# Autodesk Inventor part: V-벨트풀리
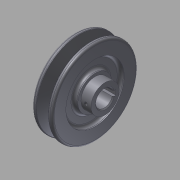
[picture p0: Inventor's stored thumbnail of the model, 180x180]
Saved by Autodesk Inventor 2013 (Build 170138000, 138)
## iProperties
Company: 한국ATC센터
Created: 2014-07
Part Number: V-벨트풀리
Document SubType Name: Modeling
Designer: KYOUNG IL JANG
Density: 7.87 g/cm^3
Material: 강철, 탄소
Mass: 593.766 g
Surface Area: 234.122 cm^2
Volume: 75.4468 cm^3
Author: KYOUNG IL JANG
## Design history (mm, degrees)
sketch "스케치1"
  geometry: L1 (-15, 0)-(15, 0); L2 (-15, 0)-(-15, 17); L3 (-15, 17)-(-11, 17); L4 (-11, 17)-(-11, 29); L5 (-11, 29)-(-15, 29); L6 (-15, 29)-(-15, 42.5); L7 (-15, 42.5)-(-10.976, 42.5); L8 (-10.976, 42.5)-(-7.154, 30); L9 (-7.154, 30)-(-2.846, 30); L10 (-2.846, 30)-(0.976, 42.5); L11 (0.976, 42.5)-(5, 42.5); L12 (5, 42.5)-(5, 29); L13 (5, 29)-(1, 29); L14 (1, 29)-(1, 17); L15 (1, 17)-(5, 17); L16 (5, 17)-(5, 14); L17 (5, 14)-(15, 14); L18 (15, 14)-(15, 0); L19 (-9.6, 38)-(-0.4, 38); 2 further points
  constraints: 38 end point, 11 parallel, 7 collinear, 3 equal length, 3 perpendicular, 2 point on line, 1 coincident, 1 horizontal, 1 midpoint
  dimensions: "d0" = 30 distance of L1.start L1.end; "d1" = 4.5 distance between parallel lines of L7 L19; "d2" = 8 distance between parallel lines of L9 L19; "d3" = 9.2 distance of L19.start L19.end; "d4" = 34 deg angle of L10 L8; "d5" = 20 distance between parallel lines of L12 L6; "d6" = 76 diameter of L19 L1; "d7" = 4 distance of L2.end L3.end; "d8" = 34 diameter of L3 L1; "d9" = 58 diameter of L5 L1; "d10" = 28 diameter of L17 L1
revolve "회전1" sketch "스케치1" stored, may be unused: angle "d11" = 90 deg
sketch "스케치2"
  geometry: L1 (-2.5, 8.124)-(-2.5, 10.8); L2 (-2.5, 10.8)-(2.5, 10.8); L3 (2.5, 10.8)-(2.5, 8.124); A1 r 8.5 centre (0, 0) between (-2.5, 8.124) and (2.5, 8.124); 1 further point
  constraints: 6 end point, 2 parallel, 2 point on circle, 1 centre point, 1 coincident, 1 horizontal, 1 vertical
  dimensions: "d12" = 17 diameter of A1; "d13" = 5 distance of L1.end L2.end; "d14" = 19.3 dimension on A1 L2 (computed from d12)
extrude "돌출1" cut sketch "스케치2" stored distance "d15" = 10; taper "d16" = 0 deg
chamfer "모따기1" distance "d17" = 1; stored, may be unused: second distance "d18" = 2, angle "d19" = 45 deg
node "작업 평면1"
sketch "스케치3"
  geometry: L1 (5, -14)-(5, 14) reference; 3 further points
  constraints: 1 horizontal alignment, 1 midpoint
  dimensions: "d20" = 5 distance from line of L1 point (0, 0)
hole "구멍1" sketch "스케치3" at (0, 0) diameter "d21" = 3.242; stored, may be unused: countersink angle "d25" = 90 deg, drill point angle "d27" = 118 deg; dims "d22" = 6, "d23" = 4, "d24" = 2, "d26" = 8
fillet "모깎기1" dims "d28" = 3, "d29" = 2, "d30" = 0.5, "d31" = 1
node "솔리드1"
